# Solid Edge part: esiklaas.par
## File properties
Author: Indrek
Template: Normal.par
Last saved by: Indrek
Revision: 5
Application: Solid Edge
Density: 2595,000 kg/m^3
Accuracy: 0,990
Material: Glass, general industrial
Face Style: White (glass)
Fill Style: ANSI36(Marble)
Virtual Style: White (Glass)
Coef. of Thermal Exp: 0.0
Thermal Conductivity: 0.0
Specific Heat: 0.0
Modulus of Elasticity: 0.0
Poission's Ratio: 0.0
Yield Stress: 0.0
Ultimate Stress: 0.0
Elongation: 0.0
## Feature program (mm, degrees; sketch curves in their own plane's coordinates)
sketch for "unnamed Protrusion 1" plane through (0, 0, 0) normal (0, 0, 1) x-axis (1, 0, 0)
  arc centre (87.2302, -34.6255) radius 106.0217 from (7.8798, 35.6888) to (-18.7861, -35.6888) ccw
  arc centre (87.2302, -34.6255) radius 106.0217 from (-18.7861, -35.6888) to (9.8164, -107.0665) ccw
  line (12.5576, -107.0665) -> (9.8164, -107.0665)
  line (18.1332, -107.0665) -> (12.5576, -107.0665)
  arc centre (89.9714, -34.6255) radius 102.0217 from (18.1332, -107.0665) to (-12.0448, -35.6888) cw
  arc centre (89.9714, -34.6255) radius 102.0217 from (-12.0448, -35.6888) to (16.0503, 35.6888) cw
  line (16.0503, 35.6888) -> (10.6209, 35.6888)
  line (10.6209, 35.6888) -> (7.8798, 35.6888)
extrude "unnamed Protrusion 1" add finite 50 along +normal
chamfer "Chamfer_1" setback 5
chamfer "Chamfer_2" setback 5
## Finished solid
Body 1: solid body, 10 faces, 24 edges, 16 vertices.
  Faces by surface: plane 6, cone 2, cylinder 2
  Edges by curve: line 10, intersection 8, circle 6
Bounding box of the edges (mm): 36.925 x 142.755 x 50.000, from (-18.7915, -107.0665, 0) to (18.1332, 35.6888, 50).
Cylindrical faces by radius (mm): R102.0217 x1, R106.0217 x1
Conical faces (half-angle, radius in mm at the cone's reference point): 45 deg R101.0217 x1, 45 deg R106.0217 x1
Planar faces by outward normal: +y 1, +z 1, -y 1, -z 1, oblique 2
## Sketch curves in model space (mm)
line (16.0503, 35.6888, 0) -> (10.6209, 35.6888, 0)
line (10.6209, 35.6888, 0) -> (7.8798, 35.6888, 0)
arc centre (87.2302, -34.6255, 0) radius 106.0217 from (7.8798, 35.6888, 0) through (-12.087, 2.4783, 0) to (-18.7861, -35.6888, 0)
arc centre (87.2302, -34.6255, 0) radius 106.0217 from (-18.7861, -35.6888, 0) through (-11.1839, -74.0621, 0) to (9.8164, -107.0665, 0)
line (12.5576, -107.0665, 0) -> (9.8164, -107.0665, 0)
line (18.1332, -107.0665, 0) -> (12.5576, -107.0665, 0)
arc centre (89.9714, -34.6255, 0) radius 102.0217 from (18.1332, -107.0665, 0) through (-3.9968, -74.3546, 0) to (-12.0448, -35.6888, 0)
arc centre (89.9714, -34.6255, 0) radius 102.0217 from (-12.0448, -35.6888, 0) through (-4.9611, 2.741, 0) to (16.0503, 35.6888, 0)
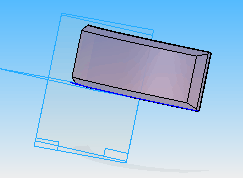
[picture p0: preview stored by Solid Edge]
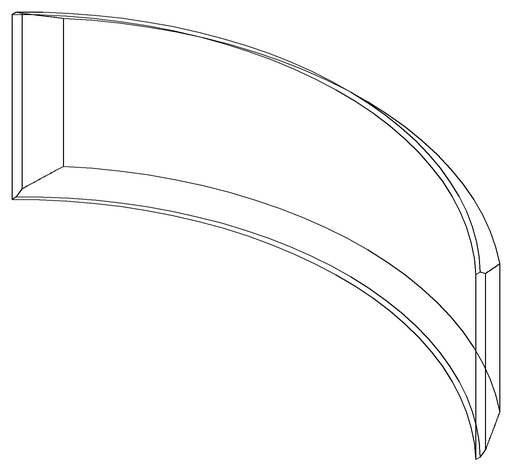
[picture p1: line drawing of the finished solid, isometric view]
